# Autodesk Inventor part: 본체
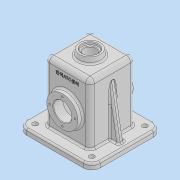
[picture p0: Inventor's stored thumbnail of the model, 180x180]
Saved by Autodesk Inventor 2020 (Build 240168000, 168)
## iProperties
Created: 2022-11
Part Number: 본체
Material: 일반
Document SubType Name: Modeling
Designer: user
Density: 1 g/cm^3
Appearance: 기본값
Author: user
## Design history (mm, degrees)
sketch "스케치1"
  geometry: L1 (62, 65)-(-62, 65); L2 (-62, 65)-(-62, -65); L3 (-62, -65)-(62, -65); L4 (62, -65)-(62, 65); L5 (62, 65)-(-62, -65); L6 (-62, 65)-(62, -65); 1 further point
  constraints: 12 end point, 2 midpoint, 2 parallel, 1 horizontal, 1 perpendicular
  dimensions: "d0" = 124 distance of L3.end L2.end; "d1" = 130 distance of L2.end L1.end
extrude "돌출1" new body sketch "스케치1" distance "d2" = 10; taper "d3" = 0 deg
sketch "스케치2"
  geometry: L1 (-40, -40)-(40, -40); L2 (40, -40)-(40, 40); L3 (40, 40)-(-40, 40); L4 (-40, 40)-(-40, -40); L5 (-40, -40)-(40, 40); L6 (40, -40)-(-40, 40); 1 further point
  constraints: 12 end point, 2 midpoint, 2 parallel, 1 horizontal, 1 perpendicular
  dimensions: "d4" = 80 distance of L3.end L2.end; "d5" = 80 distance of L2.end L1.end
extrude "돌출2" join sketch "스케치2" distance "d6" = 107; taper "d7" = 0 deg
fillet "모깎기1" dims "d8" = 8
sketch "스케치3"
  geometry: L1 (-33, -10)-(97, -10) reference; C1 r 27.5 at (32, 45); 2 further points
  constraints: 1 centre point, 1 midpoint, 1 vertical alignment
  dimensions: "d9" = 55 diameter of C1; "d10" = 55 distance from line of L1 C1.centre
extrude "돌출3" join sketch "스케치3" distance "d11" = 9; taper "d12" = 0 deg
sketch "스케치4"
  geometry: C1 r 27.5 at (32, 45) reference; C2 r 16 at (32, 45); 1 further point
  constraints: 1 centre point, 1 coincident
  dimensions: "d13" = 32 diameter of C2
extrude "돌출4" cut sketch "스케치4" extent not by distance; stored distance "d14" = 9; taper "d15" = 0 deg
fillet "모깎기2" dims "d16" = 15
fillet "모깎기3" dims "d17" = 3
sketch "스케치5"
  geometry: C1 r 16 at (0, 0) reference; C2 r 27.5 at (0, 0) reference; A1 r 22.5 centre (0, 0) between (0, 22.5) and (-22.5, 0); 3 further points
  constraints: 4 point on circle, 2 horizontal alignment, 2 vertical alignment, 1 centre point, 1 coincident
  dimensions: "d18" = 45 diameter of A1
hole "구멍1" sketch "스케치5" at (0, 22.5), (-22.5, 0), (0, -22.5), (22.5, 0) diameter "d19" = 3.242; stored, may be unused: countersink angle "d23" = 90 deg, drill point angle "d25" = 118 deg; dims "d20" = 8, "d21" = 4, "d22" = 2, "d24" = 10
sketch "스케치6"
  geometry: L1 (-32, -32)-(32, -32); L2 (32, -32)-(32, 32); L3 (32, 32)-(-32, 32); L4 (-32, 32)-(-32, -32); L5 (-32, -32)-(32, 32); L6 (32, -32)-(-32, 32); 2 further points
  constraints: 12 end point, 2 midpoint, 2 parallel, 1 coincident, 1 horizontal, 1 perpendicular
  dimensions: "d26" = 64 distance of L3.end L2.end; "d27" = 64 distance of L2.end L1.end
extrude "돌출5" cut sketch "스케치6" distance "d28" = 109; taper "d29" = 0 deg
fillet "모깎기4" dims "d30" = 3
chamfer "모따기1" distance "d31" = 1; stored, may be unused: second distance "d32" = 2, angle "d33" = 45 deg
sketch "스케치8"
  geometry: C1 r 20 at (0, 0); 1 further point
  constraints: 1 centre point, 1 coincident
  dimensions: "d34" = 40 diameter of C1
extrude "돌출6" join sketch "스케치8" distance "d35" = 10; taper "d36" = -10 deg
sketch "스케치9"
  geometry: C1 r 18.237 at (0, 0) reference; C2 r 14 at (0, 0)
  constraints: 1 centre point, 1 coincident
  dimensions: "d37" = 28 diameter of C2
extrude "돌출7" cut sketch "스케치9" distance "d38" = 4; taper "d39" = 0 deg
sketch "스케치10"
  geometry: C1 r 14 at (0, 0) reference; C2 r 10.5 at (0, 0)
  constraints: 1 centre point, 1 coincident
  dimensions: "d40" = 21 diameter of C2
extrude "돌출8" cut sketch "스케치10" distance "d41" = 14; taper "d42" = 0 deg
chamfer "모따기2" distance "d43" = 1; stored, may be unused: second distance "d44" = 2, angle "d45" = 45 deg
fillet "모깎기5" dims "d46" = 3
fillet "모깎기6" dims "d47" = 3
fillet "모깎기7" dims "d48" = 3
fillet "모깎기8" dims "d49" = 3
sketch "스케치11"
  geometry: C1 r 4.5 at (47, -50); C2 r 4.5 at (-47, -50); C3 r 4.5 at (-47, 50); C4 r 4.5 at (47, 50); A1 r 12 centre (47, -50) between (47, -62) and (59, -50) reference; A2 r 12 centre (47, 50) between (59, 50) and (47, 62) reference; A3 r 12 centre (-47, 50) between (-47, 62) and (-59, 50) reference; A4 r 12 centre (-47, -50) between (-59, -50) and (-47, -62) reference; 1 further point
  constraints: 4 centre point, 4 coincident
  dimensions: "d50" = 9 diameter of C1; "d51" = 9 diameter of C2; "d52" = 9 diameter of C3; "d53" = 9 diameter of C4
extrude "돌출9" cut sketch "스케치11" distance "d54" = 14; taper "d55" = 0 deg
fillet "모깎기9" dims "d56" = 3
sketch "스케치12"
  geometry: L1 (10, -40)-(10, -55.693); L2 (10, -55.693)-(99, -40); L3 (99, -40)-(10, -40); L4 (0, -65)-(7, -65) reference; L5 (10, -45.5)-(10, -54.5) reference; L6 (13, -40)-(109, -40) reference; L7 (10, -50)-(10, -62) reference; L8 (127, -15)-(127, 15) reference; 3 further points
  constraints: 6 end point, 2 midpoint, 2 point on line, 1 perpendicular, 1 vertical
  dimensions: "d59" = 100 deg angle of L2 L7; "d60" = 28 distance from line of L8 L2.end
extrude "돌출10" join sketch "스케치12" stored distance "d61" = 10; taper "d62" = 0 deg
fillet "모깎기10" dims "d63" = 3
fillet "모깎기11" dims "d64" = 3
node "작업 평면1"
sketch "스케치13"
  geometry: L1 (72, -96)-(72, 0) reference; L2 (13.763, 18)-(50.237, 18) reference; 2 further points
  constraints: 1 other
  dimensions: "d66" = 40 distance from line of L1 point (32, -7); "d67" = 25 distance from line of L2 point (32, -7)
feature "엠보싱1" sketch "스케치13" dims "d0" = 124, "d1" = 130, "d68" = 0.5, "d69" = 0
node "솔리드1"
mirror "미러1"
mirror "미러2"
mirror "미러3"
feature "A9D066F2-1C7D-4E18-AEED-F7BC21143FA4" dims "d19" = 3.242, "d20" = 8, "d21" = 4, "d22" = 2, "d23" = 90 deg, "d24" = 10, "d25" = 118 deg
